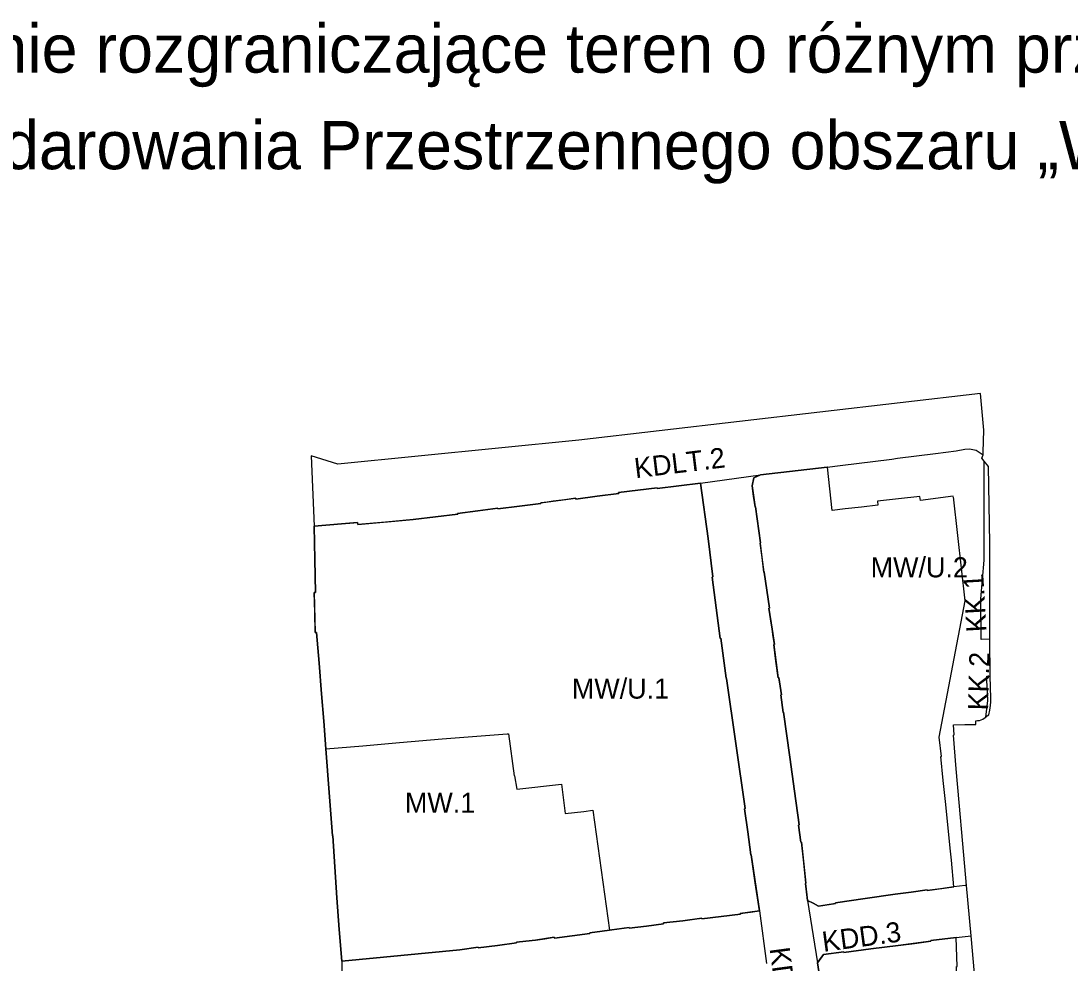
# Model space of a CAD drawing. Extents: x 7423893 to 7425332, y 5547241 to 5548246.
# Drawn here: x 7424403.1 to 7424663.7, y 5548011.5 to 5548245.6 of the extents above; entities that cross this region are included whole.
import ezdxf

# ---------------------------------------------------------------- set-up
doc = ezdxf.new("R2010")
doc.units = 0
for name, color, linetype in [('info', 7, 'Continuous'), ('linie rozgraniczające', 7, 'Continuous'), ('nieprzekraczalne linie zabudowy', 7, 'Continuous'), ('obowiazujace linie zabudowy', 7, 'Continuous'), ('przeznaczenia terenów', 7, 'Continuous')]:
    doc.layers.add(name, color=color, linetype=linetype)

msp = doc.modelspace()

# ---------------------------------------------------------------- linework, layer by layer
at = {"layer": 'linie rozgraniczające'}
for p, q in [((7424571.88, 5548130.76), (7424586.79, 5548132.79)), ((7424639.08, 5548018.22), (7424637.96, 5548030.77)), ((7424598.49, 5548027), (7424600.96, 5548011.55)), ((7424586.51, 5548024.42), (7424588.29, 5548011.39))]:
    msp.add_line(p, q, dxfattribs=at)
for points in [[(7424642.07, 5548137.79), (7424642.12, 5548138.46), (7424642.3, 5548143.87), (7424641.46, 5548153), (7424541.71, 5548141.45), (7424481.86, 5548135.47), (7424475.2, 5548137.56), (7424475.96, 5548120)], [(7424586.79, 5548132.79), (7424603.35, 5548134.72), (7424606.55, 5548135.11), (7424619.37, 5548136.69), (7424620.79, 5548136.9), (7424630.24, 5548138.08), (7424635.39, 5548138.76), (7424637.57, 5548139.15), (7424638.73, 5548139.26), (7424640.37, 5548138.96), (7424642.07, 5548137.79)], [(7424637.96, 5548030.77), (7424637.04, 5548041.07), (7424636.13, 5548051.36), (7424635.42, 5548059.75), (7424634.7, 5548068.14), (7424634.9, 5548068.17), (7424634.82, 5548069.44), (7424634.73, 5548070.7), (7424637.5, 5548070.73), (7424640.28, 5548070.76), (7424640.28, 5548071.65), (7424640.72, 5548071.71), (7424641.16, 5548071.77), (7424641.57, 5548071.92), (7424641.97, 5548072.07), (7424642.35, 5548072.33), (7424642.73, 5548072.6), (7424643.11, 5548072.87), (7424643.49, 5548073.13), (7424643.71, 5548074.32), (7424643.93, 5548075.5), (7424643.96, 5548076.38), (7424644, 5548077.27), (7424643.92, 5548080.03), (7424643.83, 5548082.78), (7424643.72, 5548091.95), (7424643.75, 5548097.09), (7424643.77, 5548102.23), (7424643.78, 5548105.69), (7424643.79, 5548115.82), (7424643.38, 5548134.87), (7424642.35, 5548136.16), (7424641.74, 5548136.93), (7424642.07, 5548137.79)], [(7424643.72, 5548091.95), (7424641.59, 5548091.91), (7424641.54, 5548101.96), (7424642.36, 5548111.57), (7424642.35, 5548136.16)], [(7424594.1, 5548062.61), (7424592.54, 5548073.78), (7424592.39, 5548073.76), (7424591.83, 5548078.12), (7424591.98, 5548078.14), (7424591.65, 5548080.26), (7424591.32, 5548082.39), (7424591.19, 5548082.38), (7424590.63, 5548086.51), (7424590.08, 5548090.65), (7424590.23, 5548090.67), (7424589.98, 5548092.57), (7424589.73, 5548094.46), (7424589.67, 5548094.45), (7424589.29, 5548097.05), (7424588.9, 5548099.65), (7424588.98, 5548099.66), (7424589.05, 5548099.67), (7424588.38, 5548104.15), (7424587.7, 5548108.63), (7424587.69, 5548108.66), (7424587.65, 5548108.65), (7424587.17, 5548112.25), (7424586.69, 5548115.85), (7424586.79, 5548115.86), (7424585.59, 5548124.84), (7424585.54, 5548124.83), (7424585.48, 5548124.83), (7424585.08, 5548127.46), (7424584.69, 5548130.09), (7424585.18, 5548132.03), (7424586.79, 5548132.79)], [(7424482.78, 5548011.96), (7424482.19, 5548019.83), (7424481.6, 5548027.69), (7424481.09, 5548035.38), (7424480.59, 5548043.06), (7424480.54, 5548043.05), (7424480.5, 5548043.05), (7424479.67, 5548053.88), (7424478.85, 5548064.72), (7424478.33, 5548071.54), (7424477.8, 5548078.35), (7424477.16, 5548085.99), (7424476.51, 5548093.62), (7424476.37, 5548093.62), (7424476.23, 5548093.61), (7424476.1, 5548098.58), (7424475.97, 5548103.56), (7424476.27, 5548103.58), (7424475.96, 5548120), (7424482.75, 5548120.58), (7424485.8, 5548120.84), (7424486.72, 5548120.92), (7424486.76, 5548120.44), (7424500.57, 5548121.69), (7424506.08, 5548122.36), (7424511.59, 5548123.03), (7424511.57, 5548123.15), (7424516.57, 5548123.82), (7424521.56, 5548124.49), (7424521.58, 5548124.4), (7424521.59, 5548124.31), (7424526.92, 5548125), (7424532.24, 5548125.69), (7424532.27, 5548125.82), (7424535.28, 5548126.23), (7424540.9, 5548126.99), (7424540.92, 5548126.79), (7424546.25, 5548127.5), (7424551.59, 5548128.2), (7424551.57, 5548128.39), (7424556.35, 5548128.99), (7424561.13, 5548129.58), (7424561.15, 5548129.42), (7424571.88, 5548130.76)], [(7424571.88, 5548130.76), (7424573.78, 5548116.94), (7424574.99, 5548107.43), (7424574.79, 5548107.4), (7424575.79, 5548099.77), (7424576.78, 5548092.14), (7424576.87, 5548092.16), (7424576.95, 5548092.17), (7424577.61, 5548087.2), (7424578.26, 5548082.23), (7424578.36, 5548082.22), (7424580.67, 5548066.03), (7424582.98, 5548049.84), (7424582.81, 5548049.81), (7424583.61, 5548044.09), (7424584.41, 5548038.37), (7424584.51, 5548038.38), (7424586.51, 5548024.42), (7424584.14, 5548024.11), (7424581.77, 5548023.8), (7424581.79, 5548023.63), (7424577, 5548023.04), (7424572.21, 5548022.45), (7424572.2, 5548022.54), (7424572.19, 5548022.62), (7424567.47, 5548021.98), (7424562.71, 5548021.43), (7424562.73, 5548021.33), (7424562.74, 5548021.24), (7424558.45, 5548020.67), (7424554.16, 5548020.1), (7424554.15, 5548020.2), (7424554.14, 5548020.3), (7424549.32, 5548019.6), (7424544.41, 5548019.01), (7424544.44, 5548018.81), (7424540.02, 5548018.25), (7424535.6, 5548017.68), (7424535.59, 5548017.78), (7424535.58, 5548017.87), (7424530.89, 5548017.17), (7424528.55, 5548016.91), (7424526.21, 5548016.64), (7424526.22, 5548016.55), (7424526.23, 5548016.47), (7424521.46, 5548015.84), (7424516.68, 5548015.21), (7424516.67, 5548015.29), (7424516.66, 5548015.38), (7424512.15, 5548014.74), (7424497.46, 5548013.35), (7424482.78, 5548011.96)], [(7424642.73, 5548072.6), (7424643.28, 5548076.69), (7424643.03, 5548081.82), (7424643, 5548082.77), (7424643.83, 5548082.78)], [(7424478.85, 5548064.72), (7424488.01, 5548065.49), (7424497.17, 5548066.26), (7424507.73, 5548067.15), (7424523.92, 5548068.42), (7424524.23, 5548068.44), (7424525.63, 5548057.98), (7424525.74, 5548057.99), (7424526.25, 5548054.64), (7424537.38, 5548055.95), (7424538.29, 5548048.62), (7424540.59, 5548048.88), (7424542.88, 5548049.16), (7424545.18, 5548049.43), (7424549.32, 5548019.6)], [(7424637.96, 5548030.77), (7424637.66, 5548030.73), (7424634.79, 5548030.39), (7424631.49, 5548029.95), (7424628.18, 5548029.5), (7424628.16, 5548029.65), (7424624.19, 5548029.12), (7424620.22, 5548028.6), (7424612.82, 5548027.5), (7424605.41, 5548026.4), (7424605.43, 5548026.25), (7424603.32, 5548025.94), (7424601.2, 5548025.63), (7424599.84, 5548026.31), (7424598.49, 5548027), (7424598.21, 5548029.13), (7424597.94, 5548031.27), (7424598.09, 5548031.29), (7424597.54, 5548036.39), (7424596.99, 5548041.49), (7424596.85, 5548041.48), (7424596.24, 5548045.77), (7424596.4, 5548045.8), (7424595.25, 5548054.21), (7424594.1, 5548062.61)], [(7424601.7, 5548006.6), (7424600.96, 5548011.55), (7424601.71, 5548012.58), (7424602.47, 5548013.62), (7424607.45, 5548014.27), (7424607.47, 5548014.11), (7424614.21, 5548014.97), (7424620.95, 5548015.83), (7424625.03, 5548016.36), (7424629.11, 5548016.88), (7424629.09, 5548017.03), (7424635.37, 5548017.85), (7424639.08, 5548018.22)], [(7424641.11, 5547994.19), (7424640.74, 5547999.53), (7424639.91, 5548008.88), (7424639.08, 5548018.22)], [(7424482.78, 5548011.96), (7424482.88, 5548004.5), (7424482.99, 5547997.04)]]:
    msp.add_lwpolyline(points, dxfattribs=at)
at = {"layer": 'nieprzekraczalne linie zabudowy'}
for points in [[(7424637.64, 5548101.49), (7424635.79, 5548117.71), (7424634.69, 5548127.35)], [(7424633.86, 5548040.05), (7424632.8, 5548050.88), (7424632.19, 5548056.84), (7424631.58, 5548062.8), (7424631.73, 5548062.81), (7424631.18, 5548067.64), (7424637.64, 5548101.49)], [(7424640.9, 5547851.91), (7424640.9, 5547851.91), (7424635.99, 5547987.05), (7424635.89, 5547992.77), (7424635.98, 5547992.77), (7424635.97, 5547993.45), (7424635.97, 5547993.45), (7424635.91, 5547998.82), (7424635.47, 5548010.62), (7424635.61, 5548010.62), (7424635.37, 5548017.85)]]:
    msp.add_lwpolyline(points, dxfattribs=at)
at = {"layer": 'obowiazujace linie zabudowy'}
for points in [[(7424604.61, 5548123.92), (7424603.43, 5548134.7), (7424603.35, 5548134.72), (7424586.79, 5548132.79), (7424585.18, 5548132.03), (7424584.69, 5548130.09), (7424585.48, 5548124.83), (7424585.59, 5548124.84), (7424586.79, 5548115.86), (7424586.69, 5548115.85), (7424586.69, 5548115.85), (7424587.15, 5548112.37), (7424587.65, 5548108.65), (7424587.69, 5548108.66), (7424587.7, 5548108.63), (7424589.05, 5548099.67), (7424588.9, 5548099.65), (7424589.67, 5548094.45), (7424589.73, 5548094.46), (7424590.23, 5548090.67), (7424590.08, 5548090.65), (7424591.19, 5548082.38), (7424591.32, 5548082.4), (7424591.98, 5548078.14), (7424591.83, 5548078.12), (7424592.39, 5548073.76), (7424592.54, 5548073.78), (7424594.1, 5548062.61), (7424595.25, 5548054.21), (7424596.4, 5548045.8), (7424596.24, 5548045.77), (7424596.85, 5548041.48), (7424596.99, 5548041.49), (7424598.09, 5548031.29), (7424597.94, 5548031.27), (7424598.49, 5548027)], [(7424482.78, 5548011.96), (7424497.46, 5548013.35), (7424512.15, 5548014.74), (7424516.66, 5548015.38), (7424516.68, 5548015.21), (7424521.46, 5548015.84), (7424526.23, 5548016.47), (7424526.21, 5548016.64), (7424528.55, 5548016.91), (7424530.89, 5548017.17), (7424533.24, 5548017.52), (7424535.58, 5548017.87), (7424535.6, 5548017.68), (7424540.02, 5548018.25), (7424544.44, 5548018.81), (7424544.41, 5548019.01), (7424546.87, 5548019.3), (7424549.32, 5548019.6), (7424551.73, 5548019.95), (7424554.14, 5548020.3), (7424554.16, 5548020.1), (7424558.45, 5548020.67), (7424562.74, 5548021.24), (7424562.71, 5548021.41), (7424562.71, 5548021.43), (7424567.47, 5548021.98), (7424569.83, 5548022.3), (7424572.19, 5548022.62), (7424572.21, 5548022.45), (7424577, 5548023.04), (7424581.79, 5548023.63), (7424581.77, 5548023.8), (7424584.29, 5548024.13), (7424586.51, 5548024.42), (7424585.51, 5548031.4), (7424584.51, 5548038.38), (7424584.41, 5548038.37), (7424583.61, 5548044.09), (7424582.81, 5548049.81), (7424582.98, 5548049.84), (7424580.67, 5548066.03), (7424578.36, 5548082.22), (7424578.26, 5548082.23), (7424576.95, 5548092.17), (7424576.78, 5548092.14), (7424575.79, 5548099.77), (7424574.79, 5548107.4), (7424574.99, 5548107.43), (7424573.78, 5548116.94), (7424571.88, 5548130.76), (7424561.15, 5548129.42), (7424561.13, 5548129.58), (7424556.35, 5548128.99), (7424551.57, 5548128.39), (7424551.59, 5548128.2), (7424546.25, 5548127.5), (7424540.92, 5548126.79), (7424540.9, 5548126.99), (7424538.09, 5548126.61), (7424535.28, 5548126.23), (7424533.78, 5548126.03), (7424532.27, 5548125.82), (7424532.24, 5548125.69), (7424526.92, 5548125), (7424521.59, 5548124.31), (7424521.56, 5548124.49), (7424516.57, 5548123.82), (7424511.57, 5548123.15), (7424511.59, 5548123.03), (7424506.08, 5548122.36), (7424500.57, 5548121.69), (7424493.67, 5548121.07), (7424486.76, 5548120.44), (7424486.72, 5548120.92), (7424482.75, 5548120.58), (7424475.96, 5548120), (7424476.12, 5548111.79), (7424476.27, 5548103.58)], [(7424634.67, 5548127.52), (7424626.49, 5548126.46), (7424626.39, 5548127.4), (7424621.1, 5548126.82), (7424615.81, 5548126.23), (7424615.92, 5548125.3), (7424611.85, 5548124.8), (7424607.78, 5548124.31), (7424604.61, 5548123.92)], [(7424476.27, 5548103.58), (7424475.97, 5548103.56), (7424476.23, 5548093.61), (7424476.51, 5548093.62), (7424477.16, 5548085.99), (7424477.8, 5548078.35), (7424478.33, 5548071.54), (7424478.85, 5548064.72), (7424479.67, 5548053.88), (7424480.5, 5548043.05), (7424480.59, 5548043.06), (7424481.09, 5548035.38), (7424481.6, 5548027.69), (7424482.19, 5548019.83), (7424482.78, 5548011.96)], [(7424598.49, 5548027), (7424599.84, 5548026.31), (7424601.2, 5548025.63), (7424605.43, 5548026.25), (7424605.41, 5548026.4), (7424612.82, 5548027.5), (7424620.22, 5548028.6), (7424624.19, 5548029.12), (7424628.16, 5548029.65), (7424628.18, 5548029.5), (7424634.79, 5548030.39), (7424634.25, 5548037.01), (7424633.86, 5548040.05)], [(7424635.37, 5548017.85), (7424629.09, 5548017.03), (7424629.11, 5548016.88), (7424620.95, 5548015.83), (7424614.21, 5548014.97), (7424607.47, 5548014.11), (7424607.45, 5548014.27), (7424602.47, 5548013.62), (7424600.96, 5548011.55), (7424601.7, 5548006.6)]]:
    msp.add_lwpolyline(points, dxfattribs=at)

# ---------------------------------------------------------------- texts
at = {"layer": 'info'}
for s, p in [('Materiał pomocniczy zawierający linie rozgraniczające teren o różnym przeznaczeniu i różnych warunkach zagospodarowania terenu, ', (7424149.65, 5548232.75)), ('opracowane w skali 1:1000 pochodzące z Miejscowego Planu Zagospodarowania Przestrzennego obszaru „WESOŁA - ZACHÓD” zatwierdzonego uchwałą RMK Nr XLIX/1346/20 z dnia 2 grudnia 2020 r.', (7423892, 5548208.75))]:
    msp.add_text(s, height=12, dxfattribs=at).set_placement(p)
at = {"layer": 'przeznaczenia terenów'}
for s, rotation, p in [('KDLT.2', 6.9275, (7424555.76, 5548131.94)), ('KK.1', 93.3727, (7424642.96, 5548093.84)), ('KK.2', 88.5284, (7424643.31, 5548074.22)), ('KDD.3', 7.6607, (7424602.44, 5548014.23)), ('KDD.1', 277.6607, (7424589.03, 5548015.08))]:
    msp.add_text(s, height=5, rotation=rotation, dxfattribs=at).set_placement(p)
for s, p in [('MW/U.2', (7424614.15, 5548107.32)), ('MW/U.1', (7424539.95, 5548077.18)), ('MW.1', (7424498.49, 5548048.81))]:
    msp.add_text(s, height=5, dxfattribs=at).set_placement(p)

doc.saveas('drawing.dxf')
